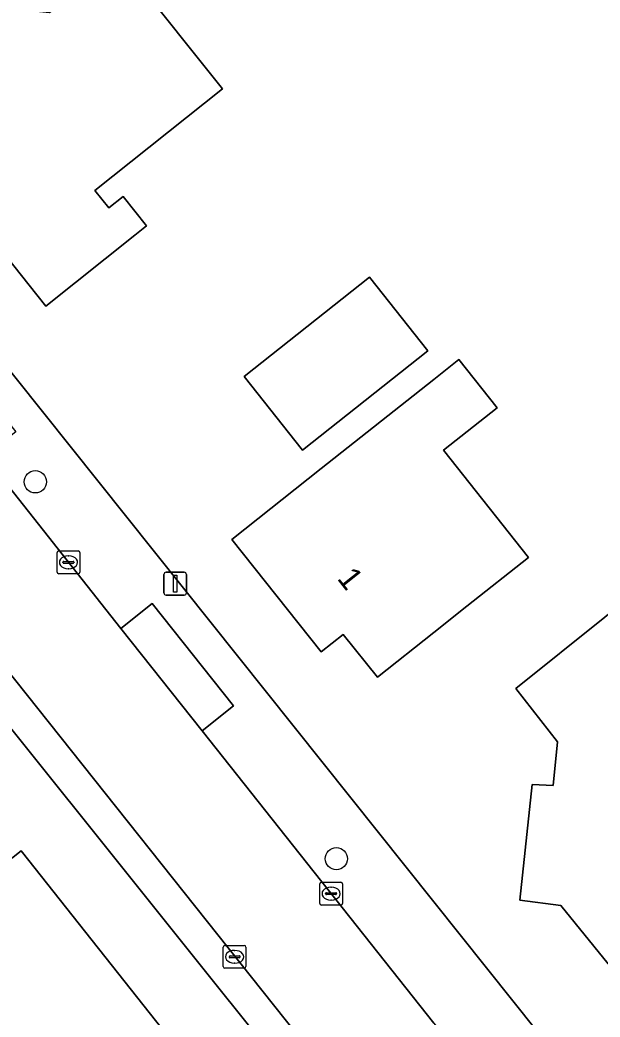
# Model space of a CAD drawing. Extents: x 159499 to 160349, y 382524 to 383273.
# Drawn here: x 159981.84 to 160007.29, y 383068.91 to 383112.66 of the extents above; entities that cross this region are included whole.
import ezdxf

# ---------------------------------------------------------------- set-up
doc = ezdxf.new("R2010")
doc.units = 0
for name, color, linetype in [('IMGEO_Boom', 7, 'Continuous'), ('IMGEO_Erf', 7, 'Continuous'), ('IMGEO_Kolk', 7, 'Continuous'), ('IMGEO_Lichtmast', 7, 'Continuous'), ('IMGEO_Pand', 7, 'Continuous'), ('IMGEO_Pand_nummerreeks', 7, 'Continuous'), ('IMGEO_Parkeervlak_open', 7, 'Continuous'), ('IMGEO_Rijbaan_lokaal_open', 7, 'Continuous')]:
    doc.layers.add(name, color=color, linetype=linetype)

msp = doc.modelspace()

# ---------------------------------------------------------------- linework, layer by layer
at = {"layer": 'IMGEO_Boom'}
for centre in [(159982.51, 383092.398), (159995.72, 383075.858)]:
    msp.add_circle(centre, 0.489, dxfattribs=at)
at = {"layer": 'IMGEO_Erf'}
for points in [[(160069.07, 383073.156), (160071.919, 383076.914), (160077.006, 383081.993), (160081.991, 383086.829), (160067.75, 383101.08), (160016.301, 383152.744), (160001.274, 383140.9), (160002.826, 383138.938), (160000, 383136.696), (159969.339, 383112.369), (160000, 383073.962), (160006.879, 383065.344), (160051.214, 383033.728), (160053.92, 383031.798), (160060.452, 383040.944)], [(159994.564, 383065.187), (159980.466, 383082.767)]]:
    msp.add_lwpolyline(points, dxfattribs=at)
for points in [[(159990.718, 383109.639), (159985.126, 383105.184), (159985.737, 383104.418), (159986.361, 383104.917), (159987.389, 383103.626), (159986.881, 383103.221), (159982.971, 383100.104), (159980.091, 383103.717), (159980.599, 383104.122), (159978.131, 383107.219), (159977.63, 383106.82), (159973.87, 383111.54), (159978.65, 383115.3), (159980.233, 383113.288), (159983.128, 383112.99), (159986.139, 383115.388), (159989.255, 383111.477)], [(159994.232, 383093.785), (159991.67, 383097.02), (159997.172, 383101.379), (159999.734, 383098.144)], [(160004.152, 383089.074), (160001.451, 383086.935), (160000, 383085.786), (159997.531, 383083.83), (159996.02, 383085.698), (159995.048, 383084.943), (159991.134, 383089.869), (159995.054, 383092.974), (160000, 383096.892), (160001.098, 383097.761), (160002.775, 383095.644), (160000.423, 383093.78)], [(160011.843, 383085.728), (160013.657, 383085.494), (160013.102, 383080.419), (160012.189, 383080.526), (160012.019, 383078.201), (160013.746, 383076.102), (160011.54, 383074.345), (160007.652, 383071.248), (160005.568, 383073.804), (160003.777, 383074.045), (160004.319, 383079.118), (160005.233, 383079.064), (160005.425, 383080.99), (160003.591, 383083.329), (160007.496, 383086.453), (160009.78, 383088.28)], [(159981.882, 383076.202), (159991.799, 383063.691), (159985.573, 383058.726), (159984.982, 383059.41), (159982.494, 383057.437), (159979.38, 383061.349), (159978.579, 383062.354), (159979.762, 383063.296), (159976.547, 383067.334), (159977.876, 383068.392), (159975.603, 383071.247), (159977.958, 383073.105)]]:
    msp.add_lwpolyline(points, close=True, dxfattribs=at)
at = {"layer": 'IMGEO_Kolk'}
for p, q in [((159983.465, 383088.436), (159983.465, 383089.288)), ((159983.54, 383089.362), (159984.392, 383089.362)), ((159983.953, 383089.142), (159983.978, 383089.142)), ((159984.466, 383089.288), (159984.466, 383088.436)), ((159983.724, 383088.856), (159983.724, 383088.868)), ((159984.162, 383088.819), (159983.764, 383088.819)), ((159983.767, 383088.905), (159984.165, 383088.905)), ((159984.208, 383088.868), (159984.208, 383088.856)), ((159984.392, 383088.362), (159983.54, 383088.362)), ((159983.976, 383088.582), (159983.951, 383088.582)), ((159994.991, 383073.898), (159994.991, 383074.75)), ((159995.066, 383074.824), (159995.918, 383074.824)), ((159995.992, 383074.75), (159995.992, 383073.898)), ((159995.25, 383074.318), (159995.25, 383074.33)), ((159995.688, 383074.281), (159995.29, 383074.281)), ((159995.293, 383074.367), (159995.691, 383074.367)), ((159995.479, 383074.604), (159995.504, 383074.604)), ((159995.734, 383074.33), (159995.734, 383074.318)), ((159995.918, 383073.824), (159995.066, 383073.824)), ((159995.502, 383074.044), (159995.477, 383074.044)), ((159990.829, 383072.053), (159991.681, 383072.053)), ((159990.754, 383071.127), (159990.754, 383071.979)), ((159991.013, 383071.547), (159991.013, 383071.559)), ((159991.056, 383071.596), (159991.454, 383071.596)), ((159991.242, 383071.833), (159991.267, 383071.833)), ((159991.497, 383071.559), (159991.497, 383071.547)), ((159991.755, 383071.979), (159991.755, 383071.127)), ((159991.451, 383071.51), (159991.053, 383071.51)), ((159991.265, 383071.273), (159991.24, 383071.273)), ((159991.681, 383071.053), (159990.829, 383071.053))]:
    msp.add_line(p, q, dxfattribs=at)
for points in [[(159983.465, 383088.436), (159983.465, 383089.288)], [(159983.54, 383089.362), (159984.392, 383089.362)], [(159984.466, 383089.288), (159984.466, 383088.436)], [(159984.392, 383088.362), (159983.54, 383088.362)], [(159994.991, 383073.898), (159994.991, 383074.75)], [(159995.066, 383074.824), (159995.918, 383074.824)], [(159995.992, 383074.75), (159995.992, 383073.898)], [(159995.918, 383073.824), (159995.066, 383073.824)], [(159990.829, 383072.053), (159991.681, 383072.053)], [(159990.754, 383071.127), (159990.754, 383071.979)], [(159991.755, 383071.979), (159991.755, 383071.127)], [(159991.681, 383071.053), (159990.829, 383071.053)]]:
    msp.add_lwpolyline(points, dxfattribs=at)
for centre, radius, start, end in [((159983.542, 383089.286), 0.0765, 91.552, 178.448), ((159983.542, 383089.286), 0.0765, 91.552, 178.448), ((159984.39, 383089.286), 0.0765, 1.552, 88.448), ((159984.39, 383089.286), 0.0765, 1.552, 88.448), ((159983.764, 383088.865), 0.0403, 85.8775, 175.7526), ((159983.761, 383088.855), 0.0366, 178.938, 274.7102), ((159984.165, 383088.862), 0.043, 264.8664, 352.4533), ((159984.169, 383088.867), 0.0386, 1.7309, 96.639), ((159983.542, 383088.438), 0.0765, 181.552, 268.448), ((159983.542, 383088.438), 0.0765, 181.552, 268.448), ((159984.39, 383088.438), 0.0765, 271.552, 358.448), ((159984.39, 383088.438), 0.0765, 271.552, 358.448), ((159995.068, 383074.748), 0.0765, 91.552, 178.448), ((159995.068, 383074.748), 0.0765, 91.552, 178.448), ((159995.916, 383074.748), 0.0765, 1.552, 88.448), ((159995.916, 383074.748), 0.0765, 1.552, 88.448), ((159995.29, 383074.327), 0.0403, 85.8775, 175.7526), ((159995.287, 383074.317), 0.0366, 178.938, 274.7102), ((159995.691, 383074.324), 0.043, 264.8664, 352.4533), ((159995.695, 383074.329), 0.0386, 1.7309, 96.639), ((159995.068, 383073.9), 0.0765, 181.552, 268.448), ((159995.068, 383073.9), 0.0765, 181.552, 268.448), ((159995.916, 383073.9), 0.0765, 271.552, 358.448), ((159995.916, 383073.9), 0.0765, 271.552, 358.448), ((159990.831, 383071.977), 0.0765, 91.552, 178.448), ((159990.831, 383071.977), 0.0765, 91.552, 178.448), ((159991.679, 383071.977), 0.0765, 1.552, 88.448), ((159991.679, 383071.977), 0.0765, 1.552, 88.448), ((159991.053, 383071.556), 0.0403, 85.8775, 175.7526), ((159991.458, 383071.558), 0.0386, 1.7309, 96.639), ((159990.831, 383071.129), 0.0765, 181.552, 268.448), ((159990.831, 383071.129), 0.0765, 181.552, 268.448), ((159991.05, 383071.546), 0.0366, 178.938, 274.7102), ((159991.454, 383071.553), 0.043, 264.8664, 352.4533), ((159991.679, 383071.129), 0.0765, 271.552, 358.448), ((159991.679, 383071.129), 0.0765, 271.552, 358.448)]:
    msp.add_arc(centre, radius, start, end, dxfattribs=at)
for centre, major_axis, ratio, start_param, end_param in [((159983.952, 383088.862), (-0.387, 0.002), 0.722429, 4.712389, 7.853982), ((159983.977, 383088.862), (-0.39, 0.002), 0.717154, 1.570796, 4.712389), ((159995.478, 383074.324), (-0.387, 0.002), 0.722429, 4.712389, 7.853982), ((159995.503, 383074.324), (-0.39, 0.002), 0.717154, 1.570796, 4.712389), ((159991.241, 383071.553), (-0.387, 0.002), 0.722429, 4.712389, 7.853982), ((159991.266, 383071.553), (-0.39, 0.002), 0.717154, 1.570796, 4.712389)]:
    msp.add_ellipse(centre, major_axis=major_axis, ratio=ratio, start_param=start_param, end_param=end_param, dxfattribs=at)
at = {"layer": 'IMGEO_Lichtmast'}
for p, q in [((159988.153, 383087.525), (159988.153, 383088.325)), ((159988.153, 383088.325), (159988.153, 383087.525)), ((159988.253, 383088.425), (159989.043, 383088.425)), ((159989.043, 383088.425), (159988.253, 383088.425)), ((159989.143, 383088.325), (159989.143, 383087.525)), ((159989.143, 383087.525), (159989.143, 383088.325)), ((159989.043, 383087.425), (159988.253, 383087.425)), ((159988.253, 383087.425), (159989.043, 383087.425))]:
    msp.add_line(p, q, dxfattribs=at)
msp.add_lwpolyline([(159988.573, 383088.3), (159988.723, 383088.3), (159988.723, 383087.55), (159988.573, 383087.55), (159988.573, 383088.3)], dxfattribs=at)
for centre, start, end in [((159988.253, 383088.325), 90, 180), ((159988.253, 383088.325), 90, 180), ((159989.043, 383088.325), 0, 90), ((159989.043, 383088.325), 360, 90), ((159988.253, 383087.525), 180, 270), ((159988.253, 383087.525), 180, 270), ((159989.043, 383087.525), 270, 0), ((159989.043, 383087.525), 270, 0)]:
    msp.add_arc(centre, 0.1, start, end, dxfattribs=at)
at = {"layer": 'IMGEO_Pand'}
for points in [[(159989.255, 383111.477), (159986.139, 383115.388), (159983.128, 383112.99), (159980.233, 383113.288), (159978.65, 383115.3), (159973.87, 383111.54), (159977.63, 383106.82), (159978.131, 383107.219), (159980.599, 383104.122), (159980.091, 383103.717), (159982.971, 383100.104), (159986.881, 383103.221), (159987.389, 383103.626), (159986.361, 383104.917), (159985.737, 383104.418), (159985.126, 383105.184), (159990.718, 383109.639)], [(159994.232, 383093.785), (159999.734, 383098.144), (159997.172, 383101.379), (159991.67, 383097.02)], [(159997.531, 383083.83), (160000, 383085.786), (160001.451, 383086.935), (160004.152, 383089.074), (160000.423, 383093.78), (160002.775, 383095.644), (160001.098, 383097.761), (160000, 383096.892), (159995.054, 383092.974), (159991.134, 383089.869), (159995.048, 383084.943), (159996.02, 383085.698)], [(160011.54, 383074.345), (160013.746, 383076.102), (160012.019, 383078.201), (160012.189, 383080.526), (160013.102, 383080.419), (160013.657, 383085.494), (160011.843, 383085.728), (160009.78, 383088.28), (160007.496, 383086.453), (160003.591, 383083.329), (160005.425, 383080.99), (160005.233, 383079.064), (160004.319, 383079.118), (160003.777, 383074.045), (160005.568, 383073.804), (160007.652, 383071.248)], [(159981.882, 383076.202), (159977.958, 383073.105), (159975.603, 383071.247), (159977.876, 383068.392), (159976.547, 383067.334), (159979.762, 383063.296), (159978.579, 383062.354), (159979.38, 383061.349), (159982.494, 383057.437), (159984.982, 383059.41), (159985.573, 383058.726), (159991.799, 383063.691)]]:
    msp.add_lwpolyline(points, close=True, dxfattribs=at)
at = {"layer": 'IMGEO_Parkeervlak_open'}
msp.add_lwpolyline([(159989.829, 383081.465), (159991.2, 383082.569), (159987.638, 383087.052), (159986.263, 383085.963)], close=True, dxfattribs=at)
at = {"layer": 'IMGEO_Rijbaan_lokaal_open'}
for points in [[(160000, 383068.637), (159989.829, 383081.465), (159986.263, 383085.963), (159980.273, 383093.518), (159973.467, 383102.103), (159966.858, 383110.439), (159961.505, 383117.191), (159957.5, 383114.019), (159962.836, 383107.311), (159995.46, 383066.299)], [(160006.879, 383065.344), (160000, 383073.962), (159969.339, 383112.369), (159966.858, 383110.439), (159973.467, 383102.103), (159974.823, 383103.191), (159981.65, 383094.597), (159980.273, 383093.518), (159986.263, 383085.963), (159987.638, 383087.052), (159991.2, 383082.569), (159989.829, 383081.465), (160000, 383068.637), (160001.834, 383066.323)], [(159995.46, 383066.299), (159962.836, 383107.311)], [(159980.466, 383082.767), (159994.564, 383065.187)]]:
    msp.add_lwpolyline(points, dxfattribs=at)

# ---------------------------------------------------------------- texts
at = {"layer": 'IMGEO_Pand_nummerreeks'}
msp.add_text('1', height=1, rotation=308.4692, dxfattribs=at).set_placement((159995.725, 383088.144))

doc.saveas('drawing.dxf')
